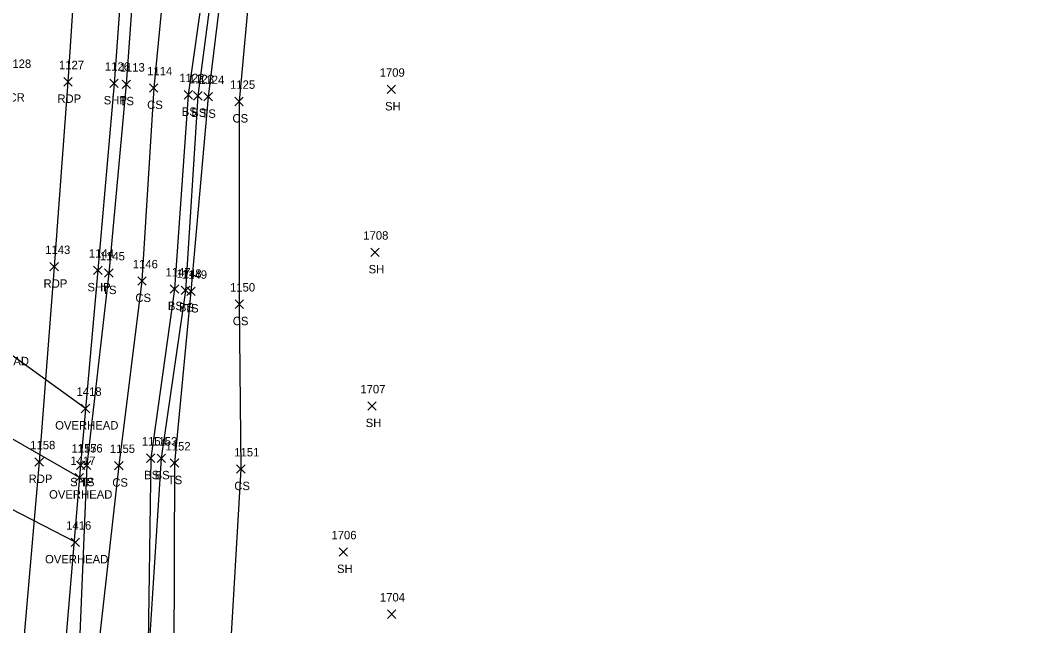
# Model space of a CAD drawing. Extents: x 1443960 to 1446865, y 610387 to 616706.
# Drawn here: x 1446612.8 to 1446852.1, y 611170.6 to 611314.4 of the extents above; entities that cross this region are included whole.
import ezdxf

# ---------------------------------------------------------------- set-up
doc = ezdxf.new("R2010")
doc.units = 0
for name, color, linetype in [('L_A', 7, 'Continuous'), ('L_I', 7, 'Continuous'), ('L_TIC', 7, 'Continuous'), ('LELB', 7, 'Continuous'), ('P_A', 7, 'Continuous'), ('P_I', 7, 'Continuous'), ('P_TIC', 7, 'Continuous'), ('PET', 7, 'Continuous'), ('PSP', 7, 'Continuous'), ('U_A', 7, 'Continuous'), ('U_I', 7, 'Continuous'), ('U_TIC', 7, 'Continuous'), ('UCO', 7, 'Continuous')]:
    doc.layers.add(name, color=color, linetype=linetype)

msp = doc.modelspace()

# ---------------------------------------------------------------- linework, layer by layer
at = {"layer": 'L_TIC'}
for points in [[(1446636.9, 611298.18), (1446638.9, 611300.18)], [(1446638.9, 611298.18), (1446636.9, 611300.18)], [(1446643.4, 611297.29), (1446645.4, 611299.29)], [(1446645.4, 611297.29), (1446643.4, 611299.29)], [(1446699.77, 611296.96), (1446701.77, 611298.96)], [(1446701.77, 611296.96), (1446699.77, 611298.96)], [(1446651.61, 611295.67), (1446653.61, 611297.67)], [(1446653.61, 611295.67), (1446651.61, 611297.67)], [(1446653.87, 611295.43), (1446655.87, 611297.43)], [(1446655.87, 611295.43), (1446653.87, 611297.43)], [(1446656.32, 611295.21), (1446658.32, 611297.21)], [(1446658.32, 611295.21), (1446656.32, 611297.21)], [(1446663.64, 611294.09), (1446665.64, 611296.09)], [(1446665.64, 611294.09), (1446663.64, 611296.09)], [(1446695.87, 611258.28), (1446697.87, 611260.28)], [(1446697.87, 611258.28), (1446695.87, 611260.28)], [(1446632.76, 611253.36), (1446634.76, 611255.36)], [(1446634.76, 611253.36), (1446632.76, 611255.36)], [(1446640.62, 611251.48), (1446642.62, 611253.48)], [(1446642.62, 611251.48), (1446640.62, 611253.48)], [(1446648.33, 611249.55), (1446650.33, 611251.55)], [(1446650.33, 611249.55), (1446648.33, 611251.55)], [(1446650.95, 611249.23), (1446652.95, 611251.23)], [(1446652.95, 611249.23), (1446650.95, 611251.23)], [(1446652.24, 611249), (1446654.24, 611251)], [(1446654.24, 611249), (1446652.24, 611251)], [(1446663.71, 611245.97), (1446665.71, 611247.97)], [(1446665.71, 611245.97), (1446663.71, 611247.97)], [(1446695.18, 611221.8), (1446697.18, 611223.8)], [(1446697.18, 611221.8), (1446695.18, 611223.8)], [(1446642.71, 611209.42), (1446644.71, 611211.42)], [(1446644.71, 611209.42), (1446642.71, 611211.42)], [(1446645.19, 611209.4), (1446647.19, 611211.4)], [(1446647.19, 611209.4), (1446645.19, 611211.4)], [(1446648.33, 611208.24), (1446650.33, 611210.24)], [(1446650.33, 611208.24), (1446648.33, 611210.24)], [(1446627.53, 611207.76), (1446629.53, 611209.76)], [(1446629.53, 611207.76), (1446627.53, 611209.76)], [(1446635.15, 611207.65), (1446637.15, 611209.65)], [(1446637.15, 611207.65), (1446635.15, 611209.65)], [(1446664.06, 611206.83), (1446666.06, 611208.83)], [(1446666.06, 611206.83), (1446664.06, 611208.83)], [(1446688.38, 611187.15), (1446690.38, 611189.15)], [(1446690.38, 611187.15), (1446688.38, 611189.15)], [(1446699.81, 611172.39), (1446701.81, 611174.39)], [(1446701.81, 611172.39), (1446699.81, 611174.39)]]:
    msp.add_lwpolyline(points, dxfattribs=at)
at = {"layer": 'LELB'}
for points in [[(1446650.95, 611452.22), (1446651.9, 611426.45), (1446649.87, 611385.11), (1446652.75, 611374.92), (1446649.16, 611347.4), (1446644.4, 611298.29), (1446641.62, 611252.48), (1446636.15, 611208.65), (1446631.11, 611163.63), (1446633.53, 611158.95), (1446637.37, 611162.3), (1446642.9, 611148.76), (1446645.64, 611144.28), (1446654.29, 611138.48), (1446692.29, 611116.85), (1446724.64, 611106.48), (1446767.02, 611093.78), (1446771.54, 611085.7), (1446779.15, 611079.3), (1446804.37, 611061.23), (1446846.91, 611054.82)], [(1446659.32, 611453.13), (1446660.37, 611426), (1446659.13, 611406.57), (1446659.21, 611386.64), (1446670.19, 611373.42), (1446674.94, 611358.1), (1446674.39, 611353.41), (1446669.38, 611345.33), (1446661.68, 611336.96), (1446656.28, 611323), (1446652.61, 611296.67), (1446649.33, 611250.55), (1446643.71, 611210.42), (1446642.98, 611161.02)], [(1446646.01, 611451.43), (1446645.8, 611427.91), (1446642.94, 611384.68), (1446641.12, 611344.07), (1446637.9, 611299.18), (1446633.76, 611254.36), (1446628.53, 611208.76), (1446626.59, 611161.02), (1446631.89, 611151.52), (1446639.4, 611144.52), (1446638.89, 611137.35), (1446641.22, 611135.35), (1446691.88, 611109.53), (1446720.61, 611092.87), (1446765.35, 611070.86), (1446803.04, 611049.45), (1446832.29, 611033.43)], [(1446674.41, 611451.43), (1446673.33, 611423.78), (1446673.4, 611405.75), (1446673.54, 611387.21), (1446676.96, 611378.49), (1446687.51, 611358.67), (1446682.52, 611348.73), (1446672.1, 611338.67), (1446667.43, 611325.36), (1446664.64, 611295.09), (1446664.71, 611246.97), (1446665.06, 611207.83), (1446662.27, 611160.47), (1446692.58, 611128.32), (1446729.03, 611120.7), (1446764.81, 611100.69), (1446774.62, 611095.27), (1446783.7, 611091.47), (1446810.78, 611080.25), (1446852.14, 611066.22)], [(1446672.1, 611338.67), (1446660.75, 611324.09), (1446657.32, 611296.21), (1446653.24, 611250), (1446649.33, 611209.24), (1446649.16, 611162.92), (1446654.29, 611138.48)], [(1446661.42, 611332.51), (1446658.36, 611323), (1446654.87, 611296.43), (1446651.95, 611250.23), (1446646.19, 611210.4), (1446642.98, 611161.02)]]:
    msp.add_lwpolyline(points, dxfattribs=at)
at = {"layer": 'P_TIC'}
for points in [[(1446623.08, 611298.75), (1446625.08, 611300.75)], [(1446625.08, 611298.75), (1446623.08, 611300.75)], [(1446634.02, 611298.39), (1446636.02, 611300.39)], [(1446636.02, 611298.39), (1446634.02, 611300.39)], [(1446619.8, 611254.87), (1446621.8, 611256.87)], [(1446621.8, 611254.87), (1446619.8, 611256.87)], [(1446630.16, 611254.01), (1446632.16, 611256.01)], [(1446632.16, 611254.01), (1446630.16, 611256.01)], [(1446616.26, 611208.52), (1446618.26, 611210.52)], [(1446618.26, 611208.52), (1446616.26, 611210.52)], [(1446626.07, 611207.74), (1446628.07, 611209.74)], [(1446628.07, 611207.74), (1446626.07, 611209.74)]]:
    msp.add_lwpolyline(points, dxfattribs=at)
at = {"layer": 'PET'}
msp.add_lwpolyline([(1446632.58, 611450.57), (1446631.62, 611430.47), (1446629.46, 611386.03), (1446626.87, 611343.17), (1446624.08, 611299.75), (1446620.8, 611255.87), (1446617.26, 611209.52), (1446613.17, 611162.1), (1446611.04, 611142.08)], dxfattribs=at)
at = {"layer": 'PSP'}
msp.add_lwpolyline([(1446643.6, 611451.3), (1446643.63, 611428.26), (1446640.44, 611385.07), (1446638.25, 611344.1), (1446635.02, 611299.39), (1446631.16, 611255.01), (1446627.07, 611208.74), (1446623.04, 611160.92), (1446621.65, 611145.45), (1446620.1, 611138.33), (1446620.36, 611137.27)], dxfattribs=at)
at = {"layer": 'U_TIC'}
for points in [[(1446627.23, 611221.21), (1446629.23, 611223.21)], [(1446629.23, 611221.21), (1446627.23, 611223.21)], [(1446625.79, 611204.81), (1446627.79, 611206.81)], [(1446627.79, 611204.81), (1446625.79, 611206.81)], [(1446624.83, 611189.44), (1446626.83, 611191.44)], [(1446626.83, 611189.44), (1446624.83, 611191.44)]]:
    msp.add_lwpolyline(points, dxfattribs=at)
at = {"layer": 'UCO'}
for points in [[(1446628.23, 611222.21), (1446607.02, 611237.47), (1446585.29, 611249.64)], [(1446626.79, 611205.81), (1446604.84, 611218.38), (1446584.03, 611231.99)], [(1446625.83, 611190.44), (1446602.81, 611202.35), (1446582.23, 611218.23)]]:
    msp.add_lwpolyline(points, dxfattribs=at)

# ---------------------------------------------------------------- texts
at = {"layer": 'L_A'}
for s, p in [('TS', (1446636.31, 611294.18)), ('CS', (1446642.85, 611293.29)), ('SH', (1446699.26, 611292.96)), ('BS', (1446651.06, 611291.67)), ('BS', (1446653.31, 611291.43)), ('TS', (1446655.73, 611291.21)), ('CS', (1446663.08, 611290.09)), ('SH', (1446695.36, 611254.28)), ('TS', (1446632.17, 611249.36)), ('CS', (1446640.06, 611247.48)), ('BS', (1446647.77, 611245.55)), ('BS', (1446650.39, 611245.23)), ('TS', (1446651.65, 611245)), ('CS', (1446663.15, 611241.97)), ('SH', (1446694.67, 611217.8)), ('TS', (1446626.94, 611203.76)), ('CS', (1446634.59, 611203.65)), ('BS', (1446642.15, 611205.42)), ('BS', (1446644.63, 611205.4)), ('TS', (1446647.74, 611204.24)), ('CS', (1446663.51, 611202.83)), ('SH', (1446687.87, 611183.15))]:
    msp.add_text(s, height=2, dxfattribs=at).set_placement(p)
at = {"layer": 'L_I'}
for s, p in [('1113', (1446636.34, 611302.18)), ('1114', (1446642.85, 611301.29)), ('1122', (1446650.49, 611299.67)), ('1123', (1446652.74, 611299.43)), ('1124', (1446655.2, 611299.21)), ('1709', (1446697.99, 611300.96)), ('1125', (1446662.51, 611298.09)), ('1708', (1446694.1, 611262.28)), ('1145', (1446631.63, 611257.36)), ('1146', (1446639.44, 611255.48)), ('1147', (1446647.2, 611253.55)), ('1148', (1446649.82, 611253.23)), ('1149', (1446651.11, 611253)), ('1150', (1446662.5, 611249.97)), ('1707', (1446693.41, 611225.8)), ('1154', (1446641.59, 611213.42)), ('1153', (1446644.06, 611213.4)), ('1156', (1446626.35, 611211.76)), ('1155', (1446634.03, 611211.65)), ('1152', (1446647.21, 611212.24)), ('1151', (1446663.51, 611210.83)), ('1706', (1446686.55, 611191.15)), ('1704', (1446698.04, 611176.39))]:
    msp.add_text(s, height=2, dxfattribs=at).set_placement(p)
at = {"layer": 'P_A'}
for s, p in [('CR', (1446609.97, 611295.05)), ('RDP', (1446621.57, 611294.75)), ('SHP', (1446632.56, 611294.39)), ('RDP', (1446618.29, 611250.87)), ('SHP', (1446628.7, 611250.01)), ('RDP', (1446614.75, 611204.52)), ('SHP', (1446624.6, 611203.74))]:
    msp.add_text(s, height=2, dxfattribs=at).set_placement(p)
at = {"layer": 'P_I'}
for s, p in [('1128', (1446609.41, 611303.05)), ('1127', (1446621.95, 611302.75)), ('1126', (1446632.84, 611302.39)), ('1143', (1446618.68, 611258.87)), ('1144', (1446629.03, 611258.01)), ('1158', (1446615.13, 611212.52)), ('1157', (1446624.94, 611211.74))]:
    msp.add_text(s, height=2, dxfattribs=at).set_placement(p)
at = {"layer": 'U_A'}
for p in [(1446599.83, 611232.47), (1446621.04, 611217.21), (1446619.6, 611200.81), (1446618.64, 611185.44)]:
    msp.add_text('OVERHEAD', height=2, dxfattribs=at).set_placement(p)
at = {"layer": 'U_I'}
for s, p in [('1418', (1446626.1, 611225.21)), ('1417', (1446624.66, 611208.81)), ('1416', (1446623.65, 611193.44))]:
    msp.add_text(s, height=2, dxfattribs=at).set_placement(p)

doc.saveas('drawing.dxf')
